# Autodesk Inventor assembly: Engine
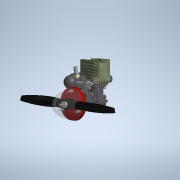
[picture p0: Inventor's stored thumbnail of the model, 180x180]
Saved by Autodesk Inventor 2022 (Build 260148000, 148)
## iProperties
Created: 2012-08
Part Number: Engine
Document SubType Name: Assembly
Designer: John
Author: John
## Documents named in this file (37)
- C:\Users\helfenj\Desktop\Ex_Files_Autodesk_Inventor_2022_Essential_Training\Exercise Files\03_Navigating the interface\03_01\Engine.iam
- C:\Users\helfenj\Desktop\Ex_Files_Autodesk_Inventor_2022_Essential_Training\Exercise Files\03_Navigating the interface\03_01\Engine Block.ipt
- C:\Users\helfenj\Desktop\Ex_Files_Autodesk_Inventor_2022_Essential_Training\Exercise Files\03_Navigating the interface\03_01\Crankshaft.ipt
- C:\Users\helfenj\Desktop\Ex_Files_Autodesk_Inventor_2022_Essential_Training\Exercise Files\03_Navigating the interface\03_01\Pulley Shaft.ipt
- C:\Users\helfenj\Desktop\Ex_Files_Autodesk_Inventor_2022_Essential_Training\Exercise Files\03_Navigating the interface\03_01\Sleeve.ipt
- C:\Users\helfenj\Desktop\Ex_Files_Autodesk_Inventor_2022_Essential_Training\Exercise Files\03_Navigating the interface\03_01\Piston Shaft.ipt
- C:\Users\helfenj\Desktop\Ex_Files_Autodesk_Inventor_2022_Essential_Training\Exercise Files\03_Navigating the interface\03_01\Piston.ipt
- C:\Users\helfenj\Desktop\Ex_Files_Autodesk_Inventor_2022_Essential_Training\Exercise Files\03_Navigating the interface\03_01\Piston Pin.ipt
- C:\Users\helfenj\Desktop\Ex_Files_Autodesk_Inventor_2022_Essential_Training\Exercise Files\03_Navigating the interface\03_01\Crank Arm.ipt
- C:\Users\helfenj\Desktop\Ex_Files_Autodesk_Inventor_2022_Essential_Training\Exercise Files\03_Navigating the interface\03_01\Face Plate.ipt
- C:\Users\helfenj\Desktop\Ex_Files_Autodesk_Inventor_2022_Essential_Training\Exercise Files\03_Navigating the interface\03_01\washer4.ipt
- C:\Users\helfenj\Desktop\Ex_Files_Autodesk_Inventor_2022_Essential_Training\Exercise Files\03_Navigating the interface\03_01\Screw Lock.ipt
- C:\Users\helfenj\Desktop\Ex_Files_Autodesk_Inventor_2022_Essential_Training\Exercise Files\03_Navigating the interface\03_01\Beveled Sleeve.ipt
- C:\Users\helfenj\Desktop\Ex_Files_Autodesk_Inventor_2022_Essential_Training\Exercise Files\03_Navigating the interface\03_01\Clutch Housing.ipt
- C:\Users\helfenj\Desktop\Ex_Files_Autodesk_Inventor_2022_Essential_Training\Exercise Files\03_Navigating the interface\03_01\Brake Pad.ipt
- C:\Users\helfenj\Desktop\Ex_Files_Autodesk_Inventor_2022_Essential_Training\Exercise Files\03_Navigating the interface\03_01\Clutch Sleeve14.ipt
- C:\Users\helfenj\Desktop\Ex_Files_Autodesk_Inventor_2022_Essential_Training\Exercise Files\03_Navigating the interface\03_01\Clutch Bearing.ipt
- C:\Users\helfenj\Desktop\Ex_Files_Autodesk_Inventor_2022_Essential_Training\Exercise Files\03_Navigating the interface\03_01\Clutch Sleeve11.ipt
- C:\Users\helfenj\Desktop\Ex_Files_Autodesk_Inventor_2022_Essential_Training\Exercise Files\03_Navigating the interface\03_01\Carburetor.iam
- C:\Users\helfenj\Desktop\Ex_Files_Autodesk_Inventor_2022_Essential_Training\Exercise Files\03_Navigating the interface\03_01\Heat Sink.ipt
- C:\Users\helfenj\Desktop\Ex_Files_Autodesk_Inventor_2022_Essential_Training\Exercise Files\03_Navigating the interface\03_01\Starter Cover.ipt
- C:\Users\helfenj\Desktop\Ex_Files_Autodesk_Inventor_2022_Essential_Training\Exercise Files\03_Navigating the interface\03_01\Horseshoe Clip.ipt
- C:\Users\helfenj\Desktop\Ex_Files_Autodesk_Inventor_2022_Essential_Training\Exercise Files\03_Navigating the interface\03_01\ANSI B18.3 - 3-48 UNC - 0.375(31).ipt
- C:\Users\helfenj\Desktop\Ex_Files_Autodesk_Inventor_2022_Essential_Training\Exercise Files\03_Navigating the interface\03_01\ANSI B18.3 - 2-56 UNC - 0.375(31).ipt
- C:\Users\helfenj\Desktop\Ex_Files_Autodesk_Inventor_2022_Essential_Training\Exercise Files\03_Navigating the interface\03_01\Muffler.ipt
- C:\Users\helfenj\Desktop\Ex_Files_Autodesk_Inventor_2022_Essential_Training\Exercise Files\03_Navigating the interface\03_01\ANSI B18.3 - 4-40 UNC - 0.875(31).ipt
- C:\Users\helfenj\Desktop\Ex_Files_Autodesk_Inventor_2022_Essential_Training\Exercise Files\03_Navigating the interface\03_01\Muffler Tip.ipt
- C:\Users\helfenj\Desktop\Ex_Files_Autodesk_Inventor_2022_Essential_Training\Exercise Files\03_Navigating the interface\03_01\Starter Handle.ipt
- C:\Users\helfenj\Desktop\Ex_Files_Autodesk_Inventor_2022_Essential_Training\Exercise Files\03_Navigating the interface\03_01\ANSI B18.3 - 1-64 UNC - UNC - 0.25(1).ipt
- C:\Users\helfenj\Desktop\Ex_Files_Autodesk_Inventor_2022_Essential_Training\Exercise Files\03_Navigating the interface\03_01\Clutch Prop Mount.ipt
- C:\Users\helfenj\Desktop\Ex_Files_Autodesk_Inventor_2022_Essential_Training\Exercise Files\03_Navigating the interface\03_01\Prop Mount.ipt
- C:\Users\helfenj\Desktop\Ex_Files_Autodesk_Inventor_2022_Essential_Training\Exercise Files\03_Navigating the interface\03_01\Prop.ipt
- C:\Users\helfenj\Desktop\Ex_Files_Autodesk_Inventor_2022_Essential_Training\Exercise Files\03_Navigating the interface\03_01\Cone.ipt
- C:\Users\helfenj\Desktop\Ex_Files_Autodesk_Inventor_2022_Essential_Training\Exercise Files\03_Navigating the interface\03_01\Crankshaft Cover.ipt
- C:\Users\helfenj\Desktop\Ex_Files_Autodesk_Inventor_2022_Essential_Training\Exercise Files\03_Navigating the interface\03_01\ANSI B18.3 - 10-24 UNC - UNC - 0.5(1).ipt
- C:\Users\helfenj\Desktop\Ex_Files_Autodesk_Inventor_2022_Essential_Training\Exercise Files\03_Navigating the interface\03_01\ANSI B18.2.2 - 1_4 - 20(3).ipt
- C:\Users\helfenj\Desktop\Ex_Files_Autodesk_Inventor_2022_Essential_Training\Exercise Files\03_Navigating the interface\03_01\ASME B18.21.1 - No. 10. Carbon Steel(4).ipt
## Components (50 placed, 36 different names)
1. Engine Block:1 — Mate:1, Mate:2, Insert:1, Mate:8, Insert:2, Mate:16, Mate:21, Flush:1, Mate:42, Angle:1, Mate:43, Mate:47, Mate:49, Mate:50, Mate:51, Mate:57, Mate:58, Mate:59, Flush:3
2. Crankshaft:1 — Mate:1, Mate:2, Mate:3, Mate:4, Mate:11, Mate:13, Mate:23, Mate:24, Mate:25, Angle:6, DRIVE THIS
3. Pulley Shaft:1 — Mate:3, Mate:4, Mate:7, Mate:17, Mate:18, Mate:19
4. Sleeve:1 — Mate:7, Mate:20
5. Piston Shaft:1 — Insert:1, Mate:8, Mate:12, Mate:48
6. Piston:1 — Mate:10, Mate:12, Mate:14, Mate:15
7. Piston Pin:1 — Mate:9, Mate:10, Mate:14, Mate:15
8. Crank Arm:1 — Mate:9, Mate:11, Mate:13
9. Face Plate:1 — Insert:2, Mate:16, Mate:17, Mate:52, Mate:60, Mate:61, DRIVE THIS
10. washer4:1 — Mate:18, Mate:19, Mate:20
11. Screw Lock:1 — Mate:21, Flush:1
12. Beveled Sleeve:1 — Mate:23, Flush:2
13. Clutch Housing:1 — Mate:24, Flush:2, Mate:27, Mate:29, Mate:30, Mate:31, Mate:32, Mate:47
14. Brake Pad:1 — Mate:31, Mate:32, Tangent:2
15. Brake Pad:2 — Mate:29, Mate:30, Tangent:1, Mate:41
16. Clutch Sleeve14:1 — Mate:25, Mate:27, Mate:33, Mate:34, Mate:37, Mate:39, Mate:53, Mate:54
17. Clutch Bearing:1 — Mate:33, Mate:35
18. Clutch Prop Mount:1 — Mate:34, Mate:35, Tangent:1, Tangent:2, Mate:38, Mate:41, Mate:62, Mate:63, Mate:68
19. Clutch Bearing:2 — Mate:37, Mate:38, Mate:40
20. Clutch Sleeve11:1 — Mate:39, Mate:40
21. Carburetor:1 [sub-assembly] — Mate:42, Angle:1, Mate:43
22. Heat Sink:1 — Mate:48, Mate:49, Mate:50, Mate:51
23. Starter Cover:1 — Mate:52, Mate:60, Mate:61, Insert:13
24. Horseshoe Clip:1 — Mate:53, Mate:54
25. Muffler Tip:1 — Mate:55, Angle:2, Mate:56
26. Muffler:1 — Mate:55, Angle:2, Mate:56, Mate:57, Mate:58, Mate:59
27. Starter Handle:1 — Insert:13
28. Hexagon Socket Head Cap Screw - Inch No. 3 - 48 UNC - 3/8:1
29. Hexagon Socket Head Cap Screw - Inch No. 3 - 48 UNC - 3/8:2
30. Hexagon Socket Head Cap Screw - Inch No. 3 - 48 UNC - 3/8:3
31. Hexagon Socket Head Cap Screw - Inch No. 3 - 48 UNC - 3/8:4
32. Hexagon Socket Head Cap Screw - Inch No. 2 - 56 UNC - 3/8:1
33. Hexagon Socket Head Cap Screw - Inch No. 2 - 56 UNC - 3/8:2
34. Hexagon Socket Head Cap Screw - Inch No. 2 - 56 UNC - 3/8:3
35. Hexagon Socket Head Cap Screw - Inch No. 2 - 56 UNC - 3/8:4
36. Hexagon Socket Head Cap Screw - Inch No. 4 - 40 UNC - 7/8:1
37. Hexagon Socket Head Cap Screw - Inch No. 4 - 40 UNC - 7/8:2
38. Hexagon Socket Button Head Cap Screw - Inch 1 - 64 x 1/4:1
39. Hexagon Socket Button Head Cap Screw - Inch 1 - 64 x 1/4:2
40. Hexagon Socket Button Head Cap Screw - Inch 1 - 64 x 1/4:3
41. Hexagon Socket Button Head Cap Screw - Inch 1 - 64 x 1/4:4
42. Prop Mount:1 — Mate:62, Mate:63, Mate:64, Mate:65, Mate:66, Mate:67, Angle:4
43. Prop:1 — Mate:64, Mate:65, Angle:4, Mate:68, Angle:5, Angle:6
44. Cone:1 — Mate:66, Mate:67, Angle:5
45. Crankshaft Cover:1 — Flush:3
46. Hexagon Socket Button Head Cap Screw - Inch 10 - 24 x 1/2:1
47. Hexagon Socket Button Head Cap Screw - Inch 10 - 24 x 1/2:2
48. Hexagon Socket Button Head Cap Screw - Inch 10 - 24 x 1/2:3
49. External Tooth Lock Washer - Type A (Inch) No. 10. Carbon Steel:1 — Mate:70
50. Hex Jam Nut - Inch 1/4 - 20:1 — Mate:70
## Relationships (74: Mate 60, Angle 6, Insert 3, Flush 3, Tangent 2)
- Mate:1: Engine Block:1 ↔ Crankshaft:1
- Mate:2: Engine Block:1 ↔ Crankshaft:1
- Mate:3: Crankshaft:1 ↔ Pulley Shaft:1
- Mate:4: Crankshaft:1 ↔ Pulley Shaft:1
- Mate:7: Pulley Shaft:1 ↔ Sleeve:1
- Insert:1: Engine Block:1 ↔ Piston Shaft:1
- Mate:8: Engine Block:1 ↔ Piston Shaft:1
- Mate:9: Piston Pin:1 ↔ Crank Arm:1
- Mate:10: Piston:1 ↔ Piston Pin:1
- Mate:11: Crankshaft:1 ↔ Crank Arm:1
- Mate:12: Piston Shaft:1 ↔ Piston:1
- Mate:13: Crankshaft:1 ↔ Crank Arm:1
- Mate:14: Piston:1 ↔ Piston Pin:1
- Mate:15: Piston:1 ↔ Piston Pin:1
- Insert:2: Engine Block:1 ↔ Face Plate:1
- Mate:16: Engine Block:1 ↔ Face Plate:1
- Mate:17: Pulley Shaft:1 ↔ Face Plate:1
- Mate:18: Pulley Shaft:1 ↔ washer4:1
- Mate:19: Pulley Shaft:1 ↔ washer4:1
- Mate:20: Sleeve:1 ↔ washer4:1
- Mate:21: Engine Block:1 ↔ Screw Lock:1
- Flush:1: Engine Block:1 ↔ Screw Lock:1
- Mate:23: Crankshaft:1 ↔ Beveled Sleeve:1
- Mate:24: Crankshaft:1 ↔ Clutch Housing:1
- Flush:2: Beveled Sleeve:1 ↔ Clutch Housing:1
- Mate:25: Crankshaft:1 ↔ Clutch Sleeve14:1
- Mate:27: Clutch Housing:1 ↔ Clutch Sleeve14:1
- Mate:29: Clutch Housing:1 ↔ Brake Pad:2
- Mate:30: Clutch Housing:1 ↔ Brake Pad:2
- Mate:31: Clutch Housing:1 ↔ Brake Pad:1
- Mate:32: Clutch Housing:1 ↔ Brake Pad:1
- Mate:33: Clutch Sleeve14:1 ↔ Clutch Bearing:1
- Mate:34: Clutch Sleeve14:1 ↔ Clutch Prop Mount:1
- Mate:35: Clutch Bearing:1 ↔ Clutch Prop Mount:1
- Tangent:1: Brake Pad:2 ↔ Clutch Prop Mount:1
- Tangent:2: Brake Pad:1 ↔ Clutch Prop Mount:1
- Mate:37: Clutch Sleeve14:1 ↔ Clutch Bearing:2
- Mate:38: Clutch Prop Mount:1 ↔ Clutch Bearing:2
- Mate:39: Clutch Sleeve14:1 ↔ Clutch Sleeve11:1
- Mate:40: Clutch Bearing:2 ↔ Clutch Sleeve11:1
- Mate:41: Brake Pad:2 ↔ Clutch Prop Mount:1
- Mate:42: Engine Block:1 ↔ Carburetor:1
- Angle:1: Engine Block:1 ↔ Carburetor:1
- Mate:43: Engine Block:1 ↔ Carburetor:1
- Mate:47: Engine Block:1 ↔ Clutch Housing:1
- Mate:48: Piston Shaft:1 ↔ Heat Sink:1
- Mate:49: Engine Block:1 ↔ Heat Sink:1
- Mate:50: Engine Block:1 ↔ Heat Sink:1
- Mate:51: Engine Block:1 ↔ Heat Sink:1
- Mate:52: Face Plate:1 ↔ Starter Cover:1
- Mate:53: Clutch Sleeve14:1 ↔ Horseshoe Clip:1
- Mate:54: Clutch Sleeve14:1 ↔ Horseshoe Clip:1
- Mate:55: Muffler Tip:1 ↔ Muffler:1
- Angle:2: Muffler Tip:1 ↔ Muffler:1
- Mate:56: Muffler Tip:1 ↔ Muffler:1
- Mate:57: Engine Block:1 ↔ Muffler:1
- Mate:58: Engine Block:1 ↔ Muffler:1
- Mate:59: Engine Block:1 ↔ Muffler:1
- Mate:60: Face Plate:1 ↔ Starter Cover:1
- Mate:61: Face Plate:1 ↔ Starter Cover:1
- Insert:13: Starter Cover:1 ↔ Starter Handle:1
- Angle:6: Crankshaft:1 ↔ Prop:1
- DRIVE THIS [Angle]: Crankshaft:1 ↔ Face Plate:1
- Mate:62: Clutch Prop Mount:1 ↔ Prop Mount:1
- Mate:63: Clutch Prop Mount:1 ↔ Prop Mount:1
- Mate:64: Prop Mount:1 ↔ Prop:1
- Mate:65: Prop Mount:1 ↔ Prop:1
- Mate:66: Prop Mount:1 ↔ Cone:1
- Mate:67: Prop Mount:1 ↔ Cone:1
- Angle:4: Prop Mount:1 ↔ Prop:1
- Mate:68: Clutch Prop Mount:1 ↔ Prop:1
- Angle:5: Prop:1 ↔ Cone:1
- Flush:3: Engine Block:1 ↔ Crankshaft Cover:1
- Mate:70: External Tooth Lock Washer - Type A (Inch) No. 10. Carbon Steel:1 ↔ Hex Jam Nut - Inch 1/4 - 20:1
